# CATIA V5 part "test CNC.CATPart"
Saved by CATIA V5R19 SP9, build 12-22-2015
Part number: test CNC
Bounding box of the stored display mesh (mm): x 0 to 50, y 0 to 35, z 0 to 20
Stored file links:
  Z:\Perso\GRBL\test CNC.CATPart
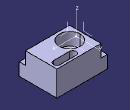
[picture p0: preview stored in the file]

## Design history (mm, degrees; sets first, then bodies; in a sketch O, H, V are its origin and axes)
AxisSystem1: origin (0, 0, 0), X (1, 0, 0), Y (0, 1, 0), Z (0, 0, 1)
Body1 (main body)
  Sketch1 on XY plane of AxisSystem1, origin (0, 0, 0), H (1, 0, 0), V (0, 1, 0)
    line L1 (10, 5) -> (50, 5)
    line L2 (50, 5) -> (50, 35)
    line L3 (50, 35) -> (10, 35)
    line L4 (10, 35) -> (10, 5)
    reference intersected line E1 through (0, 0) direction (0, 1) from YZ plane of AxisSystem1
    reference projected line E2 through (0, 0) direction (1, 0) from edge [XY plane of AxisSystem1 | ZX plane of AxisSystem1]
    distance L4 E1 = 10
    distance L1 E2 = 5
    distance L1 L3 = 30
    distance L2 L4 = 40
    horizontal: L1 H, L3 H
    vertical: L2 V, L4 V
  Pad1: profile Sketch1, direction (0, 0, 1), length 20
  Sketch2 on end face of Pad1, origin (0, 0, 20), H (1, 0, 0), V (0, 1, 0)
    construction line L1 (45.5823, 30.5686) -> (33.0433, 30.5686)
    line L2 (45.5823, 27.8808) -> (33.0433, 27.8808)
    line L3 (33.0433, 33.2563) -> (45.5823, 33.2563)
    arc A1 centre (33.0433, 30.5686) radius 2.6877 from (33.0433, 27.8808) to (33.0433, 33.2563) cw
    arc A2 centre (45.5823, 30.5686) radius 2.6877 from (45.5823, 33.2563) to (45.5823, 27.8808) cw
    circle A3 centre (25.1713, 20.3697) radius 8.3591
    construction line L4 (10, 5) -> (10, 35)
    point P8 (10, 5)
    line L5 (5, 5) -> (5, 35)
    line L6 (15, 35) -> (15, 10)
    arc A4 centre (10, 35) radius 5 from (5, 35) to (15, 35) cw
    construction line L7 (10, 5) -> (50, 5)
    point P12 (10, 5)
    line L8 (15, 10) -> (50, 10)
    line L9 (50, 0) -> (10, 0)
    arc A5 centre (50, 5) radius 5 from (50, 10) to (50, 0) cw
    arc A6 centre (10, 5) radius 5 from (10, 0) to (5, 5) cw
    point P16 (10, 0)
    point P17 (10, 5)
    reference intersected line E1 through (0, 0) direction (-1, 0) from ZX plane of AxisSystem1
    reference intersected line E2 through (0, 0) direction (0, 1) from YZ plane of AxisSystem1
    distance L1 L2 = 2.6877
    length L7 = 40
    distance P17 E1 = 5
    distance P17 E2 = 10
    length L4 = 30
    angle L4 L7 = 90
    distance L8 A6 = 10 (reference)
    distance A6 L8 = 10 (reference)
    horizontal: L1 H, L7 H
    tangency: A1 L2, A2 L2, A1 L3, A2 L3, A4 L5, A4 L6, A5 L8, A6 L8, A5 L9, A6 L9, L5 A6, L6 A6
    coincidence: P17 P8, P12 P17, P16 L9
  Pocket1: profile Sketch2, direction (0, 0, -1), length 10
